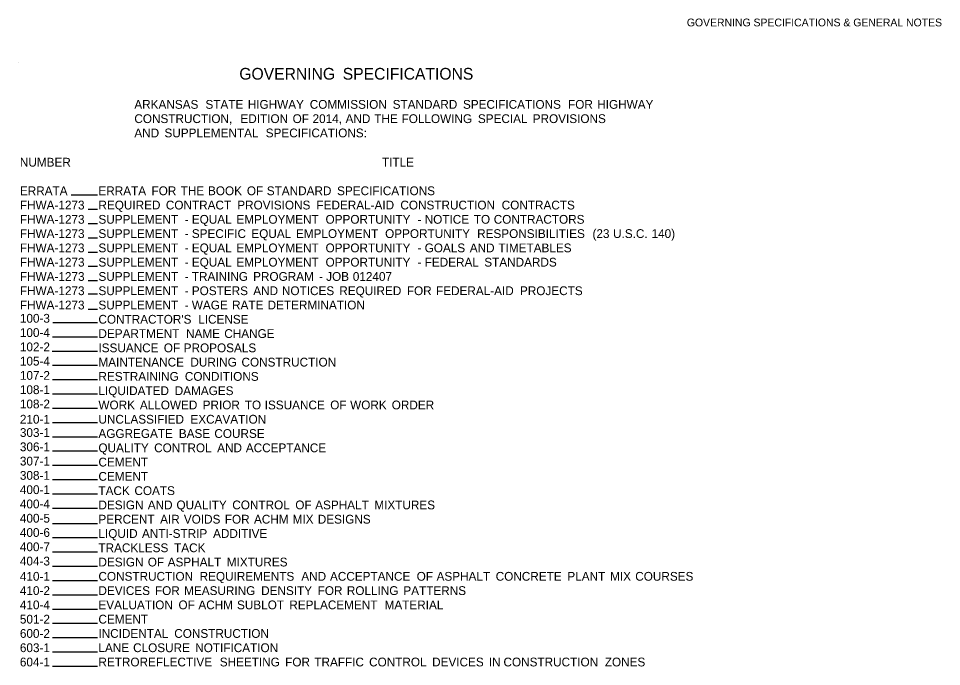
# Model space of a CAD drawing. Extents: x 1930579 to 1932218, y 596452 to 599480.
# Drawn here: x 1931524 to 1932218, y 598993 to 599480 of the extents above; entities that cross this region are included whole.
import ezdxf

# ---------------------------------------------------------------- set-up
doc = ezdxf.new("R2010")
doc.units = 0
for name, color, linetype in [('Default', 7, 'Continuous'), ('R_Border', 7, 'Continuous'), ('R_Border Prem', 7, 'Continuous')]:
    doc.layers.add(name, color=color, linetype=linetype)

msp = doc.modelspace()

# ---------------------------------------------------------------- linework, layer by layer
at = {"layer": 'R_Border'}
for p, q in [((1931524.27, 599446.28), (1931524.27, 599446.28)), ((1931563.85, 599346.97), (1931583.71, 599346.97)), ((1931576.5, 599336.24), (1931583.71, 599336.24)), ((1931576.5, 599325.52), (1931583.71, 599325.52)), ((1931576.5, 599314.79), (1931583.71, 599314.79)), ((1931576.5, 599304.07), (1931583.71, 599304.07)), ((1931576.5, 599293.34), (1931583.71, 599293.34)), ((1931576.5, 599282.62), (1931583.71, 599282.62)), ((1931576.5, 599272.64), (1931583.53, 599272.64)), ((1931576.5, 599261.17), (1931583.53, 599261.17)), ((1931550.12, 599251.19), (1931583.53, 599251.19)), ((1931549.9, 599240.46), (1931583.53, 599240.46)), ((1931549.66, 599229.74), (1931583.53, 599229.74)), ((1931549.9, 599219.01), (1931583.53, 599219.01)), ((1931549.9, 599208.29), (1931583.53, 599208.29)), ((1931549.9, 599197.56), (1931583.53, 599197.56)), ((1931549.9, 599186.84), (1931583.53, 599186.84)), ((1931549.9, 599176.11), (1931583.53, 599176.11)), ((1931549.9, 599165.39), (1931583.53, 599165.39)), ((1931549.9, 599154.66), (1931583.53, 599154.66)), ((1931549.9, 599143.94), (1931583.53, 599143.94)), ((1931549.9, 599133.21), (1931583.53, 599133.21)), ((1931549.9, 599122.49), (1931583.53, 599122.49)), ((1931549.9, 599111.76), (1931583.53, 599111.76)), ((1931549.9, 599100.29), (1931583.53, 599100.29)), ((1931549.9, 599089.57), (1931583.53, 599089.57)), ((1931549.9, 599078.84), (1931583.53, 599078.84)), ((1931549.9, 599068.12), (1931583.53, 599068.12)), ((1931549.9, 599057.39), (1931583.53, 599057.39)), ((1931549.9, 599046.67), (1931583.53, 599046.67)), ((1931549.9, 599035.94), (1931583.53, 599035.94)), ((1931549.9, 599025.22), (1931583.53, 599025.22)), ((1931549.9, 599014.49), (1931583.53, 599014.49)), ((1931549.9, 599003.77), (1931583.53, 599003.77)), ((1931549.9, 598993.04), (1931583.53, 598993.04))]:
    msp.add_line(p, q, dxfattribs=at)

# ---------------------------------------------------------------- texts
at = {"layer": 'Default'}
for s, height, p in [('GOVERNING', 8.8, (1931690.13, 599433.56)), (' SPECIFICATIONS', 8.8, (1931764.54, 599433.56)), ('           ARKANSAS', 6.6, (1931584.33, 599411.67)), (' STATE', 6.6, (1931662.24, 599411.67)), (' HIGHWAY', 6.6, (1931694.04, 599411.67)), (' COMMISSION', 6.6, (1931740.59, 599411.67)), (' STANDARD', 6.6, (1931802.85, 599411.67)), (' SPECIFICATIONS', 6.6, (1931855.65, 599411.67)), (' FOR', 6.6, (1931934.59, 599411.67)), (' HIGHWAY', 6.6, (1931956.5, 599411.67)), ('           CONSTRUCTION,', 6.6, (1931584.33, 599400.94)), (' EDITION', 6.6, (1931688.52, 599400.94)), (' OF', 6.6, (1931727.73, 599400.94)), (' 2014,', 6.6, (1931742.68, 599400.94)), (' AND', 6.6, (1931767.48, 599400.94)), (' THE', 6.6, (1931789.02, 599400.94)), (' FOLLOWING', 6.6, (1931809.54, 599400.94)), (' SPECIAL', 6.6, (1931866.85, 599400.94)), (' PROVISIONS', 6.6, (1931908.04, 599400.94)), ('           AND', 6.6, (1931584.33, 599390.22)), (' SUPPLEMENTAL', 6.6, (1931631.47, 599390.22)), (' SPECIFICATIONS:', 6.6, (1931707.51, 599390.22)), ('NUMBER', 6.6, (1931525.34, 599368.23)), ('TITLE', 6.6, (1931797.24, 599368.23)), ('ERRATA', 6.6, (1931525.34, 599346.78)), ('ERRATA', 6.6, (1931584.33, 599346.78)), (' FOR', 6.6, (1931621.75, 599346.78)), (' THE', 6.6, (1931643.66, 599346.78)), (' BOOK', 6.6, (1931664.17, 599346.78)), (' OF', 6.6, (1931693.36, 599346.78)), (' STANDARD', 6.6, (1931708.31, 599346.78)), (' SPECIFICATIONS', 6.6, (1931761.11, 599346.78)), ('FHWA-1273', 6.6, (1931525.34, 599336.06)), ('REQUIRED', 6.6, (1931584.33, 599336.06)), (' CONTRACT', 6.6, (1931632.51, 599336.06)), (' PROVISIONS', 6.6, (1931686.12, 599336.06)), (' FEDERAL-AID', 6.6, (1931745.6, 599336.06)), (' CONSTRUCTION', 6.6, (1931808.65, 599336.06)), (' CONTRACTS', 6.6, (1931884.74, 599336.06)), ('FHWA-1273', 6.6, (1931525.34, 599325.33)), ('SUPPLEMENT', 6.6, (1931584.33, 599325.33)), (' -', 6.6, (1931646.66, 599325.33)), (' EQUAL', 6.6, (1931652.01, 599325.33)), (' EMPLOYMENT', 6.6, (1931685.51, 599325.33)), (' OPPORTUNITY', 6.6, (1931752.45, 599325.33)), (' -', 6.6, (1931821.55, 599325.33)), (' NOTICE', 6.6, (1931826.89, 599325.33)), (' TO', 6.6, (1931863.8, 599325.33)), (' CONTRACTORS', 6.6, (1931878.76, 599325.33)), ('FHWA-1273', 6.6, (1931525.34, 599314.61)), ('SUPPLEMENT', 6.6, (1931584.33, 599314.61)), (' SPECIFIC', 6.6, (1931652.01, 599314.61)), (' EQUAL', 6.6, (1931696.73, 599314.61)), (' EMPLOYMENT', 6.6, (1931730.23, 599314.61)), (' OPPORTUNITY', 6.6, (1931797.17, 599314.61)), (' RESPONSIBILITIES', 6.6, (1931866.28, 599314.61)), (' (23', 6.6, (1931952.92, 599314.61)), (' U.S.C.', 6.6, (1931968.38, 599314.61)), (' 140)', 6.6, (1931997.29, 599314.61)), (' -', 6.6, (1931646.66, 599314.61)), ('FHWA-1273', 6.6, (1931525.34, 599303.88)), ('SUPPLEMENT', 6.6, (1931584.33, 599303.88)), (' -', 6.6, (1931646.66, 599303.88)), (' EQUAL', 6.6, (1931652.01, 599303.88)), (' EMPLOYMENT', 6.6, (1931685.51, 599303.88)), (' OPPORTUNITY', 6.6, (1931752.45, 599303.88)), (' -', 6.6, (1931821.55, 599303.88)), (' GOALS', 6.6, (1931826.89, 599303.88)), (' AND', 6.6, (1931860.75, 599303.88)), (' TIMETABLES', 6.6, (1931882.29, 599303.88)), ('FHWA-1273', 6.6, (1931525.34, 599293.16)), ('SUPPLEMENT', 6.6, (1931584.33, 599293.16)), (' EQUAL', 6.6, (1931652.01, 599293.16)), (' EMPLOYMENT', 6.6, (1931685.51, 599293.16)), (' OPPORTUNITY', 6.6, (1931752.45, 599293.16)), (' FEDERAL', 6.6, (1931826.89, 599293.16)), (' STANDARDS', 6.6, (1931871.66, 599293.16)), (' -', 6.6, (1931646.66, 599293.16)), (' -', 6.6, (1931821.55, 599293.16)), ('FHWA-1273', 6.6, (1931525.34, 599282.43)), ('SUPPLEMENT', 6.6, (1931584.33, 599282.43)), (' -', 6.6, (1931646.66, 599282.43)), (' TRAINING', 6.6, (1931652.01, 599282.43)), (' PROGRAM', 6.6, (1931698.05, 599282.43)), (' -', 6.6, (1931747.57, 599282.43)), (' JOB', 6.6, (1931752.91, 599282.43)), (' 012407', 6.6, (1931772.92, 599282.43)), ('FHWA-1273', 6.6, (1931525.34, 599271.71)), ('SUPPLEMENT', 6.6, (1931584.33, 599271.71)), (' POSTERS', 6.6, (1931652.01, 599271.71)), (' AND', 6.6, (1931698.16, 599271.71)), (' NOTICES', 6.6, (1931719.7, 599271.71)), (' REQUIRED', 6.6, (1931762.77, 599271.71)), (' FOR', 6.6, (1931813.52, 599271.71)), (' FEDERAL-AID', 6.6, (1931835.42, 599271.71)), (' PROJECTS', 6.6, (1931898.47, 599271.71)), (' -', 6.6, (1931646.66, 599271.71)), ('FHWA-1273', 6.6, (1931525.34, 599260.98)), ('SUPPLEMENT', 6.6, (1931584.33, 599260.98)), (' -', 6.6, (1931646.66, 599260.98)), (' WAGE', 6.6, (1931652.01, 599260.98)), (' RATE', 6.6, (1931682.26, 599260.98)), (' DETERMINATION', 6.6, (1931708.92, 599260.98)), ('100-3', 6.6, (1931525.34, 599251)), ("CONTRACTOR'S", 6.6, (1931584.33, 599250.26)), (' LICENSE', 6.6, (1931656.83, 599250.26)), ('100-4', 6.6, (1931525.34, 599240.27)), ('DEPARTMENT', 6.6, (1931584.33, 599239.53)), (' NAME', 6.6, (1931647.68, 599239.53)), (' CHANGE', 6.6, (1931676.39, 599239.53)), ('102-2', 6.6, (1931525.34, 599229.55)), ('ISSUANCE', 6.6, (1931584.33, 599228.81)), (' OF', 6.6, (1931630.98, 599228.81)), (' PROPOSALS', 6.6, (1931645.93, 599228.81)), ('105-4', 6.6, (1931525.34, 599218.82)), ('MAINTENANCE', 6.6, (1931584.33, 599218.08)), (' DURING', 6.6, (1931650.96, 599218.08)), (' CONSTRUCTION', 6.6, (1931689.32, 599218.08)), ('107-2', 6.6, (1931525.34, 599208.1)), ('RESTRAINING', 6.6, (1931584.33, 599207.36)), (' CONDITIONS', 6.6, (1931646.78, 599207.36)), ('108-1', 6.6, (1931525.34, 599197.37)), ('LIQUIDATED', 6.6, (1931584.33, 599196.63)), (' DAMAGES', 6.6, (1931639.17, 599196.63)), ('108-2', 6.6, (1931525.34, 599186.65)), ('WORK', 6.6, (1931584.33, 599185.91)), (' ALLOWED', 6.6, (1931613, 599185.91)), (' PRIOR', 6.6, (1931660.16, 599185.91)), (' TO', 6.6, (1931691.8, 599185.91)), (' ISSUANCE', 6.6, (1931706.75, 599185.91)), (' OF', 6.6, (1931755.97, 599185.91)), (' WORK', 6.6, (1931770.92, 599185.91)), (' ORDER', 6.6, (1931802.15, 599185.91)), ('210-1', 6.6, (1931525.34, 599175.18)), ('UNCLASSIFIED', 6.6, (1931584.33, 599175.18)), (' EXCAVATION', 6.6, (1931650.97, 599175.18)), ('303-1', 6.6, (1931525.34, 599165.2)), ('AGGREGATE', 6.6, (1931584.33, 599164.46)), (' BASE', 6.6, (1931642.26, 599164.46)), (' COURSE', 6.6, (1931668.93, 599164.46)), ('306-1', 6.6, (1931525.34, 599154.47)), ('QUALITY', 6.6, (1931584.33, 599153.73)), (' CONTROL', 6.6, (1931623.72, 599153.73)), (' AND', 6.6, (1931671.04, 599153.73)), (' ACCEPTANCE', 6.6, (1931692.58, 599153.73)), ('307-1', 6.6, (1931525.34, 599143.75)), ('CEMENT', 6.6, (1931584.33, 599143.01)), ('308-1', 6.6, (1931525.34, 599133.02)), ('CEMENT', 6.6, (1931584.33, 599132.28)), ('400-1', 6.6, (1931525.34, 599122.3)), ('TACK', 6.6, (1931584.33, 599121.56)), (' COATS', 6.6, (1931608.91, 599121.56)), ('400-4', 6.6, (1931525.34, 599111.57)), ('DESIGN', 6.6, (1931584.33, 599110.83)), (' AND', 6.6, (1931618.93, 599110.83)), (' QUALITY', 6.6, (1931640.47, 599110.83)), (' CONTROL', 6.6, (1931682.42, 599110.83)), (' OF', 6.6, (1931729.74, 599110.83)), (' ASPHALT', 6.6, (1931744.69, 599110.83)), (' MIXTURES', 6.6, (1931789.09, 599110.83)), ('400-5', 6.6, (1931525.34, 599100.85)), ('PERCENT', 6.6, (1931584.33, 599100.11)), (' AIR', 6.6, (1931628.21, 599100.11)), (' VOIDS', 6.6, (1931646.02, 599100.11)), (' FOR', 6.6, (1931676.8, 599100.11)), (' ACHM', 6.6, (1931698.7, 599100.11)), (' MIX', 6.6, (1931727.72, 599100.11)), (' DESIGNS', 6.6, (1931746.62, 599100.11)), ('400-6', 6.6, (1931525.34, 599090.12)), ('LIQUID', 6.6, (1931584.33, 599089.38)), (' ANTI-STRIP', 6.6, (1931614.58, 599089.38)), (' ADDITIVE', 6.6, (1931667.97, 599089.38)), ('400-7', 6.6, (1931525.34, 599079.4)), ('TRACKLESS', 6.6, (1931584.33, 599078.66)), (' TACK', 6.6, (1931638.69, 599078.66)), ('404-3', 6.6, (1931525.34, 599068.67)), ('DESIGN', 6.6, (1931584.33, 599067.93)), (' OF', 6.6, (1931618.93, 599067.93)), (' ASPHALT', 6.6, (1931633.88, 599067.93)), (' MIXTURES', 6.6, (1931678.28, 599067.93)), ('410-1', 6.6, (1931525.34, 599057.21)), ('CONSTRUCTION', 6.6, (1931584.33, 599057.21)), (' REQUIREMENTS', 6.6, (1931657.86, 599057.21)), (' AND', 6.6, (1931734.24, 599057.21)), (' ACCEPTANCE', 6.6, (1931755.78, 599057.21)), (' OF', 6.6, (1931820.89, 599057.21)), (' ASPHALT', 6.6, (1931835.83, 599057.21)), (' CONCRETE', 6.6, (1931880.24, 599057.21)), (' PLANT', 6.6, (1931934.06, 599057.21)), (' MIX', 6.6, (1931966.16, 599057.21)), (' COURSES', 6.6, (1931985.05, 599057.21)), ('410-2', 6.6, (1931525.34, 599046.48)), ('DEVICES', 6.6, (1931584.33, 599046.48)), (' FOR', 6.6, (1931624.33, 599046.48)), (' MEASURING', 6.6, (1931646.24, 599046.48)), (' DENSITY', 6.6, (1931704.07, 599046.48)), (' FOR', 6.6, (1931746.53, 599046.48)), (' ROLLING', 6.6, (1931768.44, 599046.48)), (' PATTERNS', 6.6, (1931810.9, 599046.48)), ('410-4', 6.6, (1931525.34, 599035.76)), ('EVALUATION', 6.6, (1931584.33, 599035.76)), (' OF', 6.6, (1931642, 599035.76)), (' ACHM', 6.6, (1931656.94, 599035.76)), (' SUBLOT', 6.6, (1931685.96, 599035.76)), (' REPLACEMENT', 6.6, (1931725.24, 599035.76)), (' MATERIAL', 6.6, (1931796.79, 599035.76)), ('501-2', 6.6, (1931525.34, 599025.03)), ('CEMENT', 6.6, (1931584.33, 599025.03)), ('600-2', 6.6, (1931525.34, 599014.31)), ('INCIDENTAL', 6.6, (1931584.33, 599014.31)), (' CONSTRUCTION', 6.6, (1931638.83, 599014.31)), ('603-1', 6.6, (1931525.34, 599003.58)), ('LANE', 6.6, (1931584.33, 599003.58)), (' CLOSURE', 6.6, (1931607.92, 599003.58)), (' NOTIFICATION', 6.6, (1931654.58, 599003.58)), ('604-1', 6.6, (1931525.34, 598992.86)), ('RETROREFLECTIVE', 6.6, (1931584.33, 598992.86)), (' SHEETING', 6.6, (1931673, 598992.86)), (' FOR', 6.6, (1931722.13, 598992.86)), (' TRAFFIC', 6.6, (1931744.03, 598992.86)), (' CONTROL', 6.6, (1931785.16, 598992.86)), (' DEVICES', 6.6, (1931832.48, 598992.86)), (' IN', 6.6, (1931875.05, 598992.86)), (' CONSTRUCTION', 6.6, (1931886.08, 598992.86)), (' ZONES', 6.6, (1931962.17, 598992.86))]:
    msp.add_text(s, height=height, dxfattribs=at).set_placement(p)
at = {"layer": 'R_Border Prem'}
msp.add_text('GOVERNING SPECIFICATIONS & GENERAL NOTES', height=5.862, rotation=360, dxfattribs=at).set_placement((1932026.23, 599473.55))

doc.saveas('drawing.dxf')
